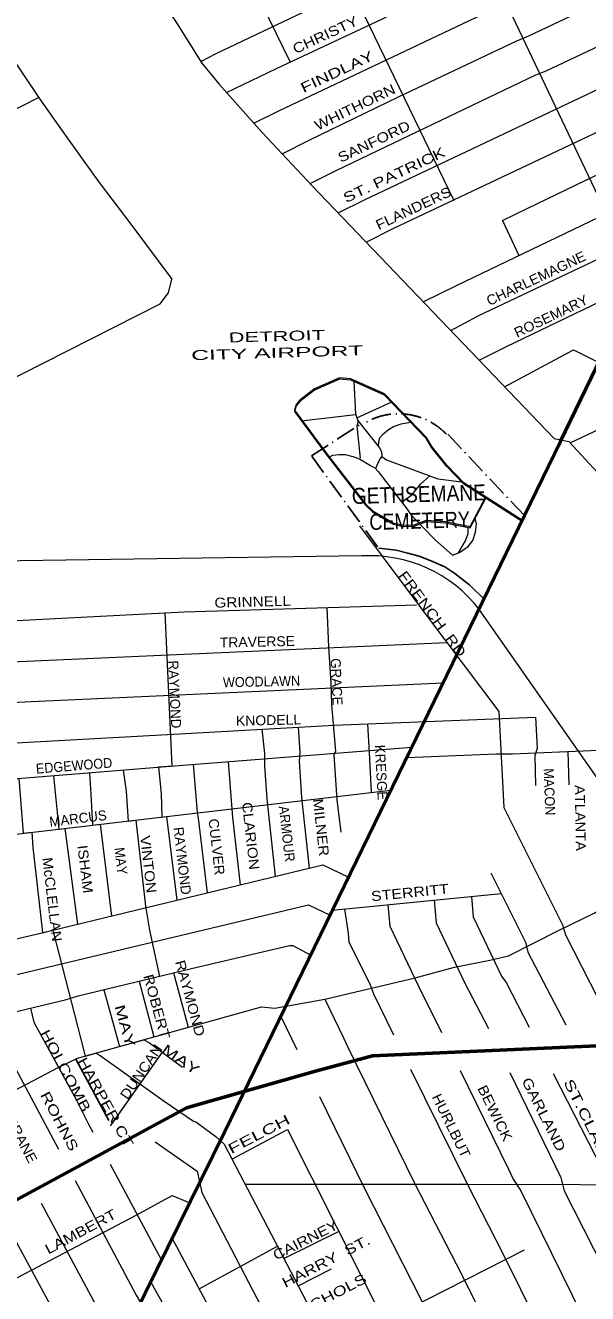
# Model space of a CAD drawing. Extents: x 34705 to 138605, y 34275 to 143551.
# Drawn here: x 109243 to 113481, y 120262 to 129823 of the extents above; entities that cross this region are included whole.
import ezdxf
from ezdxf.enums import TextEntityAlignment as Align

# ---------------------------------------------------------------- set-up
doc = ezdxf.new("R2010")
doc.units = 0
doc.header["$LTSCALE"] = 30
doc.linetypes.add('DOT_DASHED', pattern=[7.7, 5, -1.2, 0.3, -1.2])
for name, color, linetype, lineweight in [('1', 7, 'Continuous', 13), ('11', 7, 'Continuous', 13), ('3', 7, 'Continuous', 13), ('50', 7, 'Continuous', 13), ('51', 7, 'Continuous', 35)]:
    doc.layers.add(name, color=color, linetype=linetype, lineweight=lineweight)

msp = doc.modelspace()

# ---------------------------------------------------------------- linework, layer by layer
at = {"layer": '1'}
for p, q in [((112840.5, 128350.56), (112963.11, 128086.86)), ((111740.99, 126864.3), (112000.92, 126982.73)), ((111322.82, 126842.29), (111732.18, 126888.88)), ((113331.92, 124348.9), (113338.21, 124097.33)), ((111557.17, 123151.54), (112828.66, 123278.73)), ((110358.2, 122679.53), (110469.88, 122269.93)), ((110101.74, 122617.96), (110210.08, 122197.19)), ((111168.37, 122351.55), (111288.39, 122101.7)), ((110272.98, 122081.98), (109882.71, 121527.89)), ((110272.98, 122081.98), (109896.08, 121546.87)), ((110800.2, 121276.78), (111218.88, 121500.54)), ((111299.71, 120320.32), (111551.3, 120449.22))]:
    msp.add_line(p, q, dxfattribs=at)
at = {"layer": '1', "lineweight": 25}
msp.add_line((109623.22, 122030.52), (109872.03, 121566.88), dxfattribs=at)
at = {"layer": '1', "lineweight": 53}
msp.add_lwpolyline([(101368.9, 103017.54), (102548.84, 105055.11), (103212.24, 106184.42), (103282.07, 106324.13), (104294.63, 108304.78), (105138.43, 110039.49), (106145.17, 112117.65), (109289.05, 118526.78), (110743.87, 121478.11), (113275.26, 126686.61), (116465.7, 133274.74), (120395.18, 141348.71), (121157.51, 142914.61), (121243.66, 143093.14)], dxfattribs=at)
at = {"layer": '1'}
for points in [[(110564.65, 129549.38), (110680.19, 129611.61), (112452.48, 130454.59), (112756.55, 130602.33), (114340.98, 131352.97), (114410.48, 131435.53), (114579.89, 131600.66), (115718.92, 132829.32)], [(111509.73, 132520.15), (111657.77, 132426.62), (111721.73, 132374.27), (111791.51, 132252.12), (113733.61, 128168.91), (113939.82, 128058.9)], [(110964.64, 129085.26), (111152.58, 129179.26), (115363.95, 131175.91), (115511.65, 131167.22), (115611.55, 131123.76), (118086.47, 132304.59), (118081.56, 132432.35)], [(111177.7, 128855.06), (111382.8, 128957.65), (112056.1, 129283.54), (112946.6, 129705.04), (113037.82, 129744.14), (115155.45, 130745.72), (115303.14, 130754.42), (115424.77, 130706.62), (116379.33, 131166.13), (117117.79, 131522.44), (117182.95, 131544.17), (118846.65, 132335.01), (118837.96, 132447.98)], [(111388.95, 128630.48), (111591.31, 128731.69), (112199.45, 129022.83), (113089.94, 129448.66), (113168.13, 129479.08), (114942.6, 130319.89), (115159.79, 130211.26), (115789.65, 130502.39), (119505.83, 132275.26)], [(109803.64, 132159.54), (109811.62, 131991.83), (110163.92, 131547.16), (110265.83, 131596.43), (110817.56, 130421.36), (111079.22, 129868.79), (111237.62, 129546.01)], [(107380.6, 132092.9), (107509.01, 131900.23), (107729.97, 131586.13), (108276.55, 130818.35), (108706.83, 130219.24), (108840.57, 130027.3), (108921.97, 129905.15), (109090.6, 129655.04), (109352.26, 129265.33), (109520.89, 129026.85), (109672.07, 128817.45), (109799.99, 128637.14), (110038.39, 128323.04), (110347.56, 127910.69)], [(112840.5, 128350.56), (113029.13, 128444.9), (113463.52, 128653.48), (114330.11, 129066.28), (115342.23, 129548.61), (116835.44, 130253.62), (117564.12, 130602.33), (120368.08, 131927.64), (122067.69, 131958.71)], [(110853.35, 131882.09), (111358.32, 130818.35), (111404.84, 130719.47), (111457.17, 130626.4), (111579.28, 130364.66), (111686.85, 130131.99), (112471.83, 128503.36)], [(109137.12, 131674.83), (109369.7, 131394.19), (109596.48, 131080.09), (109770.92, 130812.53), (109968.62, 130498.44), (110189.57, 130143.63), (110387.27, 129835.35), (110573.34, 129538.7), (110701.26, 129381.66), (111026.89, 129015.21), (111404.84, 128613.87), (113227.73, 126708.96), (113338.21, 126685.69), (114018.53, 125952.8), (115411.14, 123991.18), (115527.43, 123880.66), (115544.77, 123865.42)], [(112242.46, 127738.56), (112493.21, 127860.75), (113690.88, 128437.04), (114226.55, 128694.85), (114363, 128760.57), (116677.5, 129852.48), (118426, 130690.37), (118552.34, 130735.87), (119936.99, 131403.15), (120376.65, 131620.52), (122075.94, 131656.69)], [(110759.06, 129316.61), (111136.29, 129498.63), (111935.56, 129872.32), (113025.87, 130406.79), (114102.06, 130922.79), (114616.19, 131148.36)], [(112662.87, 127299.24), (112868.41, 127402.04), (113774.1, 127835.49), (113960.89, 127732.28), (120307.27, 130758.76), (120750.34, 130741.38), (121167.35, 130719.65), (121393.23, 130715.31), (122101.59, 130718.5)], [(112854.63, 127098.85), (113375.55, 127377.06), (113688.31, 127220.63), (120428.89, 130395.93), (122118.66, 130309.03), (123063.45, 129791.94), (123162.27, 127218.46), (123379.46, 126788.28)], [(113348.12, 126675.01), (116020.97, 127937.6), (116268.57, 128050.57), (120507.08, 130048.31), (121532.24, 129996.17), (122123, 129922.3), (122867.97, 129505.15), (123074.46, 129505.15)], [(111601.27, 128408.6), (111804.16, 128510.08), (114573.37, 129822.36), (114749.79, 129731.45)], [(111812.18, 128188.2), (112021.35, 128292.82), (114217.17, 129331.34), (114260.61, 129374.79), (114382.24, 129431.28)], [(106336.86, 127771.32), (106393.83, 127797.22), (107275.99, 128245.84), (107344.98, 128275.42), (108379.92, 128793.06), (108453.85, 128827.57), (109342.27, 129279.46)], [(112450.16, 127521.52), (112655.56, 127632.34), (113759.25, 128155.23)], [(108436.9, 121413.01), (109494.34, 121968.63), (109634.95, 122036.15), (111021.43, 122424.37), (111122.67, 122413.12), (111499.52, 122480.64), (112180.11, 122643.81), (112478.21, 122722.58), (112743.97, 122776.02), (112884.59, 122809.78), (113267.07, 123001.08), (113531.43, 123130.49), (113790.16, 123299.29), (114144.51, 123417.44), (115235.7, 123878.81), (115432.56, 123968.84), (116653.11, 124452.72), (124173.08, 127439.91), (124643.06, 127626.95), (126069.8, 128061.11)], [(103316.6, 126694.24), (104421.29, 126723.75), (106530.59, 126768.12), (108517.91, 126840.83), (110257.59, 127723.28), (110321.66, 127807.08), (110347.56, 127910.69)], [(112983.07, 126095.98), (112548.05, 126374.01), (112420.16, 126506.13), (112306.02, 126648.01), (112266.63, 126714.79), (111950.39, 127045.18), (111696.68, 127157.25), (111609.8, 127166.43), (111422.61, 127083.7), (111310.39, 126998.47), (111283.3, 126964.31), (111270.47, 126922.37), (111514.69, 126593.4), (111805.94, 126216.61), (111861.37, 126162.01), (112016.1, 126072.83), (112089.22, 126053.88), (112173.41, 126056.32), (112266.01, 126091.8), (112406.74, 126081.84), (112595.07, 126045.16), (112712.89, 126268.66)], [(112983.36, 126086.02), (112548.35, 126364.05), (112420.45, 126496.17), (112306.31, 126638.05), (112266.92, 126704.83), (111950.68, 127035.22), (111696.97, 127147.29), (111610.09, 127156.47), (111422.9, 127073.74), (111310.68, 126988.51), (111283.59, 126954.35), (111270.76, 126912.41), (111514.98, 126583.44), (111806.23, 126206.65), (111861.66, 126152.05), (112016.4, 126062.87), (112089.51, 126043.92), (112173.7, 126046.36), (112266.3, 126081.84), (112407.03, 126071.88), (112595.36, 126035.2), (112713.18, 126258.7)], [(111717.82, 127138.08), (111731.33, 126891.26), (111750.43, 126837.95), (111742.1, 126802.57), (111766.71, 126559.72)], [(111747.32, 126846.62), (111913.08, 126637.75), (111926.18, 126610.03), (111929.02, 126572.64), (111966.04, 126547.08), (112352.87, 126405.21), (112530.12, 126382.88)], [(112147.14, 126829.96), (112071.77, 126815.38), (112021.94, 126798.12), (111979.91, 126774.65), (111933.6, 126737), (111911.51, 126711.77), (111904.71, 126684.05), (111903.01, 126650.45)], [(111527.65, 126567.05), (111560.65, 126582.72), (111606.15, 126587.55), (111652.98, 126587.16), (111710.74, 126573.03), (111760.99, 126555.17), (111844.36, 126505.48), (111880.68, 126484.29), (111902.49, 126458.58), (112067.91, 126243.53), (112120.2, 126175.96), (112150.8, 126129.72), (112197.13, 126085.98), (112245.52, 126031.77), (112332.99, 125941.8), (112462.66, 125829.35), (112515.92, 125849.05), (112580.16, 125893.66), (112614.5, 125940.62), (112635.55, 126001.54), (112643.17, 126061.48), (112632.88, 126106.38)], [(111929.22, 126572.5), (111913.75, 126554.34), (111882.21, 126482.48)], [(112079.65, 126228.36), (112158.53, 126286.57), (112223.48, 126367.49), (112292.29, 126427.43)], [(111762.44, 126050.24), (112274.13, 125363.89), (112811.98, 124651.35), (112849.78, 123927.2), (113291.7, 123043.08), (113314.95, 122967.46), (114053.42, 121519.14), (116755.93, 116340.18)], [(112507.47, 125845.92), (112561.34, 125937.32), (112581.38, 125992.93), (112581.6, 126037.88)], [(105047.2, 125274.21), (105367.52, 125279.29), (106269.39, 125303.94), (106486.24, 125289.15), (106934.71, 125249.71), (107803.31, 125273.14), (107906.81, 125278.07), (109178.3, 125337.23), (110439.94, 125401.31), (112190.71, 125455.54)], [(110292.83, 125393.84), (110346.95, 124238.67), (110247.16, 124230.99), (110265.16, 124031.89), (110271.61, 123854.8), (110306.96, 123858.95), (110383.87, 123226.97)], [(111514.29, 125434.59), (111526.95, 125137.04), (111544.39, 124863.66), (111550.21, 124700.8), (111573.46, 124439.05), (111579.28, 124351.8), (111567.65, 124322.72), (111590.91, 123985.36), (111619.98, 123741.07)], [(109066.8, 125332.04), (109139.19, 124140.51), (109193.78, 124144.98), (109227.01, 123732.2), (109292.24, 123739.86), (109299.93, 123624.73), (109369.7, 123008.18), (109372.73, 122982.47), (109448.74, 123000.85), (109451.11, 122990.73), (109683.7, 122092.08), (109694.5, 122052.82), (109774.89, 122075.33), (109805.8, 122057.18), (110288.42, 121714), (110509.38, 121562.77), (110526.82, 121556.95), (110678.01, 121446.44), (110741.97, 121388.27), (113721.98, 115682.24), (113768.5, 115595), (114188.6, 114799.58), (114229.3, 114723.97), (116785.76, 109939.79)], [(106417.87, 124932.98), (106521.96, 124932.98), (107852.6, 124962.56), (107931.45, 124962.56), (109094.52, 125021.71), (109193.09, 125026.64), (112420.19, 125170.39)], [(106426.74, 124622.18), (106975.36, 124632.25), (107832.88, 124656.9), (107906.81, 124651.97), (109286.72, 124725.92), (112391.13, 124867.47)], [(106435.61, 124311.59), (106728.95, 124316.74), (106955.65, 124326.6), (107857.52, 124346.32), (107941.3, 124346.32), (109079.74, 124415.34), (109173.37, 124415.34), (110358.62, 124479.43), (111570.98, 124548.45), (113087.96, 124607.81)], [(113087.96, 124607.81), (113099.81, 124370.71), (113082.37, 124318.36), (113088.18, 124091.52)], [(111026.03, 124517.42), (111044.33, 124334.35), (111044.33, 124241.29), (111061.77, 123991.18), (111125.73, 123409.52)], [(111298.96, 124532.96), (111311.8, 124340.17), (111305.99, 124276.19), (111323.43, 124002.81), (111382.78, 123468.5)], [(111822.6, 124558.29), (111833.32, 124338.49), (111849.17, 124042.45)], [(112117.66, 124304.76), (112791.96, 124331.53), (112915.16, 124331.53), (114216.23, 124385.76), (114698.47, 124405.86)], [(106445.46, 123966.29), (106659.95, 123971.65), (107888.16, 123997.06), (107887.39, 124038.85), (109124.09, 124139.27), (110208.31, 124228), (110784.92, 124272.37), (112154.63, 124380.85)], [(109979.81, 124209.3), (110003.5, 124049.34), (110016.57, 123824.87), (110075.55, 123831.79), (110148.87, 123182.68), (110177.94, 123002.36), (110253.53, 122653.37)], [(110508.06, 124251.07), (110538.45, 123892.3), (110544.27, 123845.76), (110613.92, 123282.59)], [(110770.58, 124271.27), (110802.81, 123852.14), (110862.41, 123342.68)], [(108665.24, 124101.95), (108697.65, 123670.07), (108762.34, 123677.67), (108858.01, 122880.22), (108863.83, 122810.42), (108997.57, 122275.29), (109491.61, 121350.64)], [(109454.57, 124166.31), (109494.1, 123763.55), (109540.39, 123768.98), (109636.75, 123046.31)], [(109725.21, 124188.46), (109736.03, 124026.08), (109749.13, 123793.48), (109807.19, 123800.29), (109892.88, 123108.25)], [(105031.02, 123494.2), (105328.09, 123503.31), (105426.66, 123508.24), (106082.12, 123518.1), (106458.26, 123517.81), (106462.62, 123365.06), (107872.31, 123389.92), (107900.16, 123389.85), (107896.3, 123575.98), (107906.81, 123577.26), (111997.4, 124057.34)], [(105027.83, 122600.11), (105204.88, 122601.14), (105288.67, 122541.99), (105392.16, 122537.06), (106427.1, 122541.99), (106525.66, 122468.04), (107919.08, 122493.56), (107915.71, 122640.31), (109365.58, 122980.74), (111485.96, 123493.45), (111678.32, 123400.81)], [(112750.93, 123434.25), (113012.59, 122910.76), (113030.04, 122835.14), (113315.42, 122289.56)], [(112604.4, 123256.3), (112617.19, 123102.7), (112832.34, 122654.83), (112867.22, 122608.29), (113041.05, 122269.66)], [(107921.99, 122368.37), (108113.79, 122413.81), (111377.54, 123192.73), (111539.66, 123115.5)], [(111647.53, 123160.58), (111675.22, 122980.55), (111681.03, 122910.76), (111838.03, 122596.66), (111867.1, 122521.05), (112018.18, 122213.2)], [(111975.84, 123193.42), (111989.21, 123032.9), (112204.35, 122585.03), (112378.32, 122231.02)], [(112323.76, 123228.22), (112338.09, 123056.17), (112553.23, 122608.29), (112732.64, 122260.23)], [(107790.96, 122022.99), (107911.74, 122088.44), (108079.3, 122132.81), (108325.71, 122191.96), (108951.6, 122334.93), (109542.99, 122477.9), (109641.56, 122507.48), (110504.01, 122714.53), (111233.39, 122887.08), (111258.03, 122887.08), (111393.51, 122814.8)], [(109834.88, 122551.59), (109939.54, 122169.15), (109952.64, 122125.11), (110134.58, 122176.05), (110177.94, 122151.7), (110426.41, 121969.43)], [(111500.38, 122480.84), (111640.33, 122189.5), (111675.22, 122113.89), (112175.28, 121094.54), (112529.97, 120408.19), (113442.88, 118562.88), (113512.65, 118464), (115060.8, 115340.52), (115130.58, 115270.73), (117546.31, 110742.66)], [(109280.54, 122414.45), (109305.74, 122307.29), (109625.55, 121725.63), (109718.58, 121539.5), (109751.03, 121479.11)], [(110898.74, 121088.09), (112569.67, 121088.09), (114286.37, 121082.27), (115928.87, 121096.83), (116446.78, 121376.24), (116487.52, 121411.17), (117156.53, 122373.91)], [(112146.29, 121953.76), (112570.68, 121094.54), (112843.97, 120559.42), (113762.68, 118702.48), (113820.83, 118626.87), (115168.43, 115907.83)], [(112519.78, 121943.18), (112884.67, 121200.69), (112919.56, 121125.07), (112977.7, 121037.82), (114059.23, 118836.26), (114117.38, 118766.46), (115636.45, 115689.52), (118019.39, 111239.65)], [(112894.44, 121929.17), (113280.07, 121136.71), (113303.32, 121037.82), (114332.52, 119016.58), (114384.85, 118935.14), (115124.76, 117466.47), (115153.84, 117385.04), (115915.56, 115866.92), (115979.52, 115808.75), (118244.33, 111511.78), (118360.62, 111453.62), (119805.57, 108692.21)], [(113220.39, 121920.32), (113640.58, 121101.81), (113623.13, 121043.64), (114618.89, 119164.9), (116241.18, 116041.41), (116281.88, 115983.25), (117113.38, 114415.69), (118526.35, 111686.28), (118604.84, 111577.22), (119553.33, 109764.96)], [(111459.91, 121748.93), (111797.32, 121059.65), (112227.61, 120210.43), (113134.7, 118388.39), (113204.48, 118283.69), (114758.44, 115154.39), (114828.22, 115107.86), (117297.53, 110480.03)], [(111218.88, 121500.54), (111954.32, 120035.93), (113582.43, 116810.66)], [(110220.41, 121405.67), (110538.45, 121186.15), (110573.34, 121023.29), (112931.19, 116490.75), (113437.06, 115531.01), (113471.95, 115467.03), (113921.13, 114601.82), (113967.64, 114566.92), (116562.83, 109704.45)], [(109880.95, 121237.35), (110269.12, 120515), (110349.58, 120678.23), (110381.46, 120617.59), (110962.92, 119529.89), (113187.03, 115385.6), (113688.54, 114468.04), (113671.1, 114369.16), (114066.49, 113636.27), (114145, 113588.3), (116342.08, 109471.41)], [(109617.34, 121115.33), (110079.09, 120251.14), (110111.31, 120194.86), (110187.4, 120349.23), (110212.83, 120303.49), (110387.27, 119995.22), (110410.53, 119931.23), (113425.43, 114313.91), (113419.62, 114220.84), (113828.05, 113455.31)], [(107421.41, 119444.69), (108231.39, 119878.74), (108784.22, 120175.62), (110081.92, 120856.7), (110349.61, 121002.23), (110349.61, 121002.23), (110482.07, 120947.02)], [(109360.57, 120944.61), (109904.65, 119931.23), (109983.15, 119784.36), (110224.46, 119335.03), (110355.29, 119092.19), (113072.15, 114039.77), (113105.05, 114057.56), (113162.65, 114094.26), (113970.56, 112576.21), (114034.52, 112465.7), (114822.4, 110976.66), (114880.55, 110874.88), (115386.42, 109926.78), (115884.46, 108988.32)], [(109100.82, 120788.27), (110073.28, 118983.13), (110134.33, 118876.98), (112785.82, 113935.83), (112832.34, 113877.67), (113605.69, 112417.71), (113640.58, 112347.91), (114095.57, 111482.7), (114473.52, 110790.53), (114816.59, 110141.99), (114845.66, 110101.28), (115591.68, 108679.26)], [(110552.79, 120297.09), (111143.86, 120618.75), (111191.19, 120528.12), (111602.85, 120731.1)], [(109584.22, 118651.54), (110745.32, 119273.34), (111607.54, 119730.9), (111547.28, 119846.29), (111565.84, 119855.46), (112272.89, 120220.74), (113006.12, 120593.29)]]:
    msp.add_lwpolyline(points, dxfattribs=at)
at = {"layer": '1', "linetype": 'DOT_DASHED', "lineweight": 25}
for points in [[(111896.99, 125892.31), (111399.2, 126578.22), (111782.59, 126824.34)], [(112427.26, 126740.1), (113004.15, 126127.35), (112702.55, 125495.43), (112591.92, 125603.22), (112480.21, 125690.8), (112403.86, 125740.05), (112311.13, 125781.26), (112218.5, 125818.76), (112126.21, 125844.75), (112037.38, 125867.32), (111907.6, 125882.9)]]:
    msp.add_lwpolyline(points, dxfattribs=at)
msp.add_arc((112055.19, 126395.03), 500, 43.5946, 122.99815, dxfattribs=at)
at = {"layer": '50'}
for p, q in [((111775.92, 125822.8), (105072.94, 125728.43)), ((114310.06, 123063.91), (112665.98, 125417.47))]:
    msp.add_line(p, q, dxfattribs=at)
msp.add_arc((111840.79, 124785.34), 1039.48, 37.45356, 93.57788, dxfattribs=at)
at = {"layer": '51', "lineweight": 60}
msp.add_lwpolyline([(107292.97, 119950.63), (110456.13, 121661.99), (111429.48, 121939.01), (111860.26, 122053.92), (113776.21, 122140.11), (114400.84, 122360.69), (114909.57, 122697.22), (116193.7, 123916.11), (116632.69, 124223.91), (116719.86, 124312.14), (117560.91, 124706.13), (118426.27, 125047.42), (119140.77, 125316.55), (119378.93, 125325.38), (119948.67, 125518.72), (120494.32, 125699.29), (120946.63, 125836.77), (121127.15, 125840.88), (124848.27, 127379.88), (125296.48, 127513.25), (126067.79, 127812.85), (126510.87, 128132.96), (126896.53, 128613.13), (127118.07, 128867.57)], dxfattribs=at)

# ---------------------------------------------------------------- texts
at = {"layer": '11'}
for s, rotation, width, p in [('CHRISTY', 25.058, 1.2, (111518.86, 129717.61)), ('FINDLAY ', 25.366, 1.4, (111624.96, 129447.49)), ('WHITHORN ', 25.828, 1.2, (111757.74, 129179.4)), ('SANFORD ', 25.582, 1.2, (111901.59, 128920.45)), ('ST. PATRICK', 25.355, 1.35, (112038.02, 128661.08)), ('FLANDERS', 25.312, 1.15, (112184.01, 128409.92)), ('CHARLEMAGNE', 25.433, 1.05, (113107.84, 127881.15)), ('ROSEMARY', 25.702, 1.05, (113221.26, 127597.71)), ('DETROIT', 1.665, 1.65, (111139.19, 127442.24)), ('CITY AIRPORT', 1.665, 1.85, (111142.83, 127317.29)), ('FRENCH  RD', 306.454, 1.25, (112280.38, 125363.96)), ('GRINNELL', 1.545, 1.15, (110956.93, 125440.07)), ('TRAVERSE', 1.285, 1.05, (110992.15, 125138.75)), ('WOODLAWN', 1.284, 0.95, (111023.71, 124839.08)), ('KNODELL', 1.284, 1.05, (111076.31, 124547.7)), ('EDGEWOOD', 4.633, 0.95, (109612.7, 124204.79)), ('MACON', 272, 0.95, (113155.94, 124043.37)), ('ATLANTA', 270.999, 1.1, (113388.28, 123847.2)), ('CLARION', 276.487, 1.15, (110904.03, 123708.07)), ('ARMOUR', 276.585, 0.95, (111176.57, 123724.13)), ('MILNER', 276.358, 1.15, (111433.9, 123772.82)), ('CULVER', 276.487, 1.05, (110647.16, 123626.18)), ('VINTON', 276.647, 1.15, (110132.41, 123494.14)), ('ISHAM', 276.904, 1.15, (109656.83, 123457.6)), ('MAY', 276.831, 0.95, (109925.72, 123518.88)), ('McCLELLAN', 276.737, 1.1, (109407.78, 123229.24)), ('STERRITT', 5.653, 1.2, (112144.86, 123248.53)), ('RAYMOND ', 285.33, 1.15, (110452.56, 122463.88)), ('ROBERT ', 285.182, 1.2, (110201.55, 122399.5)), ('MAY   ', 285.544, 1.5, (109975.07, 122211.01)), ('HOLCOMB   ', 298.023, 1.35, (109539.34, 121875.09)), ('DUNCAN', 55.491, 1.1, (110146.85, 121913.01)), ('MAY ', 325.1, 1.45, (110409.65, 121984.57)), ('HARPER CT ', 298.741, 1.3, (109823.6, 121670.2)), ('BEWICK', 296.2, 1.15, (112748.8, 121606.41)), ('GARLAND ', 296.57, 1.25, (113124.72, 121580.58)), ('ST.CLAIR   ', 296.453, 1.5, (113475.97, 121497.49)), ('ROHNS  ', 297.851, 1.35, (109483.97, 121511.31)), ('HURLBUT', 296.11, 1.1, (112419.18, 121511.21)), ('CRANE', 297.853, 1.1, (109180.29, 121407.15)), ('FELCH   ', 27.612, 1.55, (111077.7, 121460.73)), ('LAMBERT ', 28.235, 1.25, (109692.17, 120704.77)), ('CAIRNEY', 27.023, 1.2, (111370.99, 120633.5)), ('HARRY  ST.', 27.382, 1.3, (111527.09, 120472.48)), ('NICHOLS ', 27.381, 1.35, (111572.69, 120219.97))]:
    msp.add_text(s, height=75, rotation=rotation, dxfattribs=dict(at, width=width)).set_placement(p, align=Align.CENTER)
for s, rotation, p in [('RAYMOND', 272.65, (110330.92, 124777.68)), ('GRACE', 272.65, (111551.45, 124872.17)), ('KRESGE', 272.993, (111888.21, 124188.75)), ('MARCUS', 6.969, (109643.82, 123807.15)), ('RAYMOND', 276.65, (110388.54, 123520.48))]:
    msp.add_text(s, height=75, rotation=rotation, dxfattribs=at).set_placement(p, align=Align.CENTER)
at = {"layer": '3'}
for s, width, p in [('GETHSEMANE', 0.9, (112210.46, 126228.66)), ('GETHSEMANE', 0.9, (112210.46, 126228.66)), ('CEMETERY', 0.85, (112216.16, 126028.74)), ('CEMETERY', 0.85, (112216.16, 126028.74))]:
    msp.add_text(s, height=120, rotation=1.634, dxfattribs=dict(at, width=width)).set_placement(p, align=Align.CENTER)

doc.saveas('drawing.dxf')
